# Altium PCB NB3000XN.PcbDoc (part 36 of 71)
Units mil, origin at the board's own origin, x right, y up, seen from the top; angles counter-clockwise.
Board outline 9527.56 x 6929.77 mil, 6 copper layers (Top Layer, GND+SHIELD, MidLayer1, MidLayer2, P2 - 3V3+5V0, Bottom Layer), stack 62.375 mil thick; 832 components, 1027 nets, 4655 pads, 4981 vias.
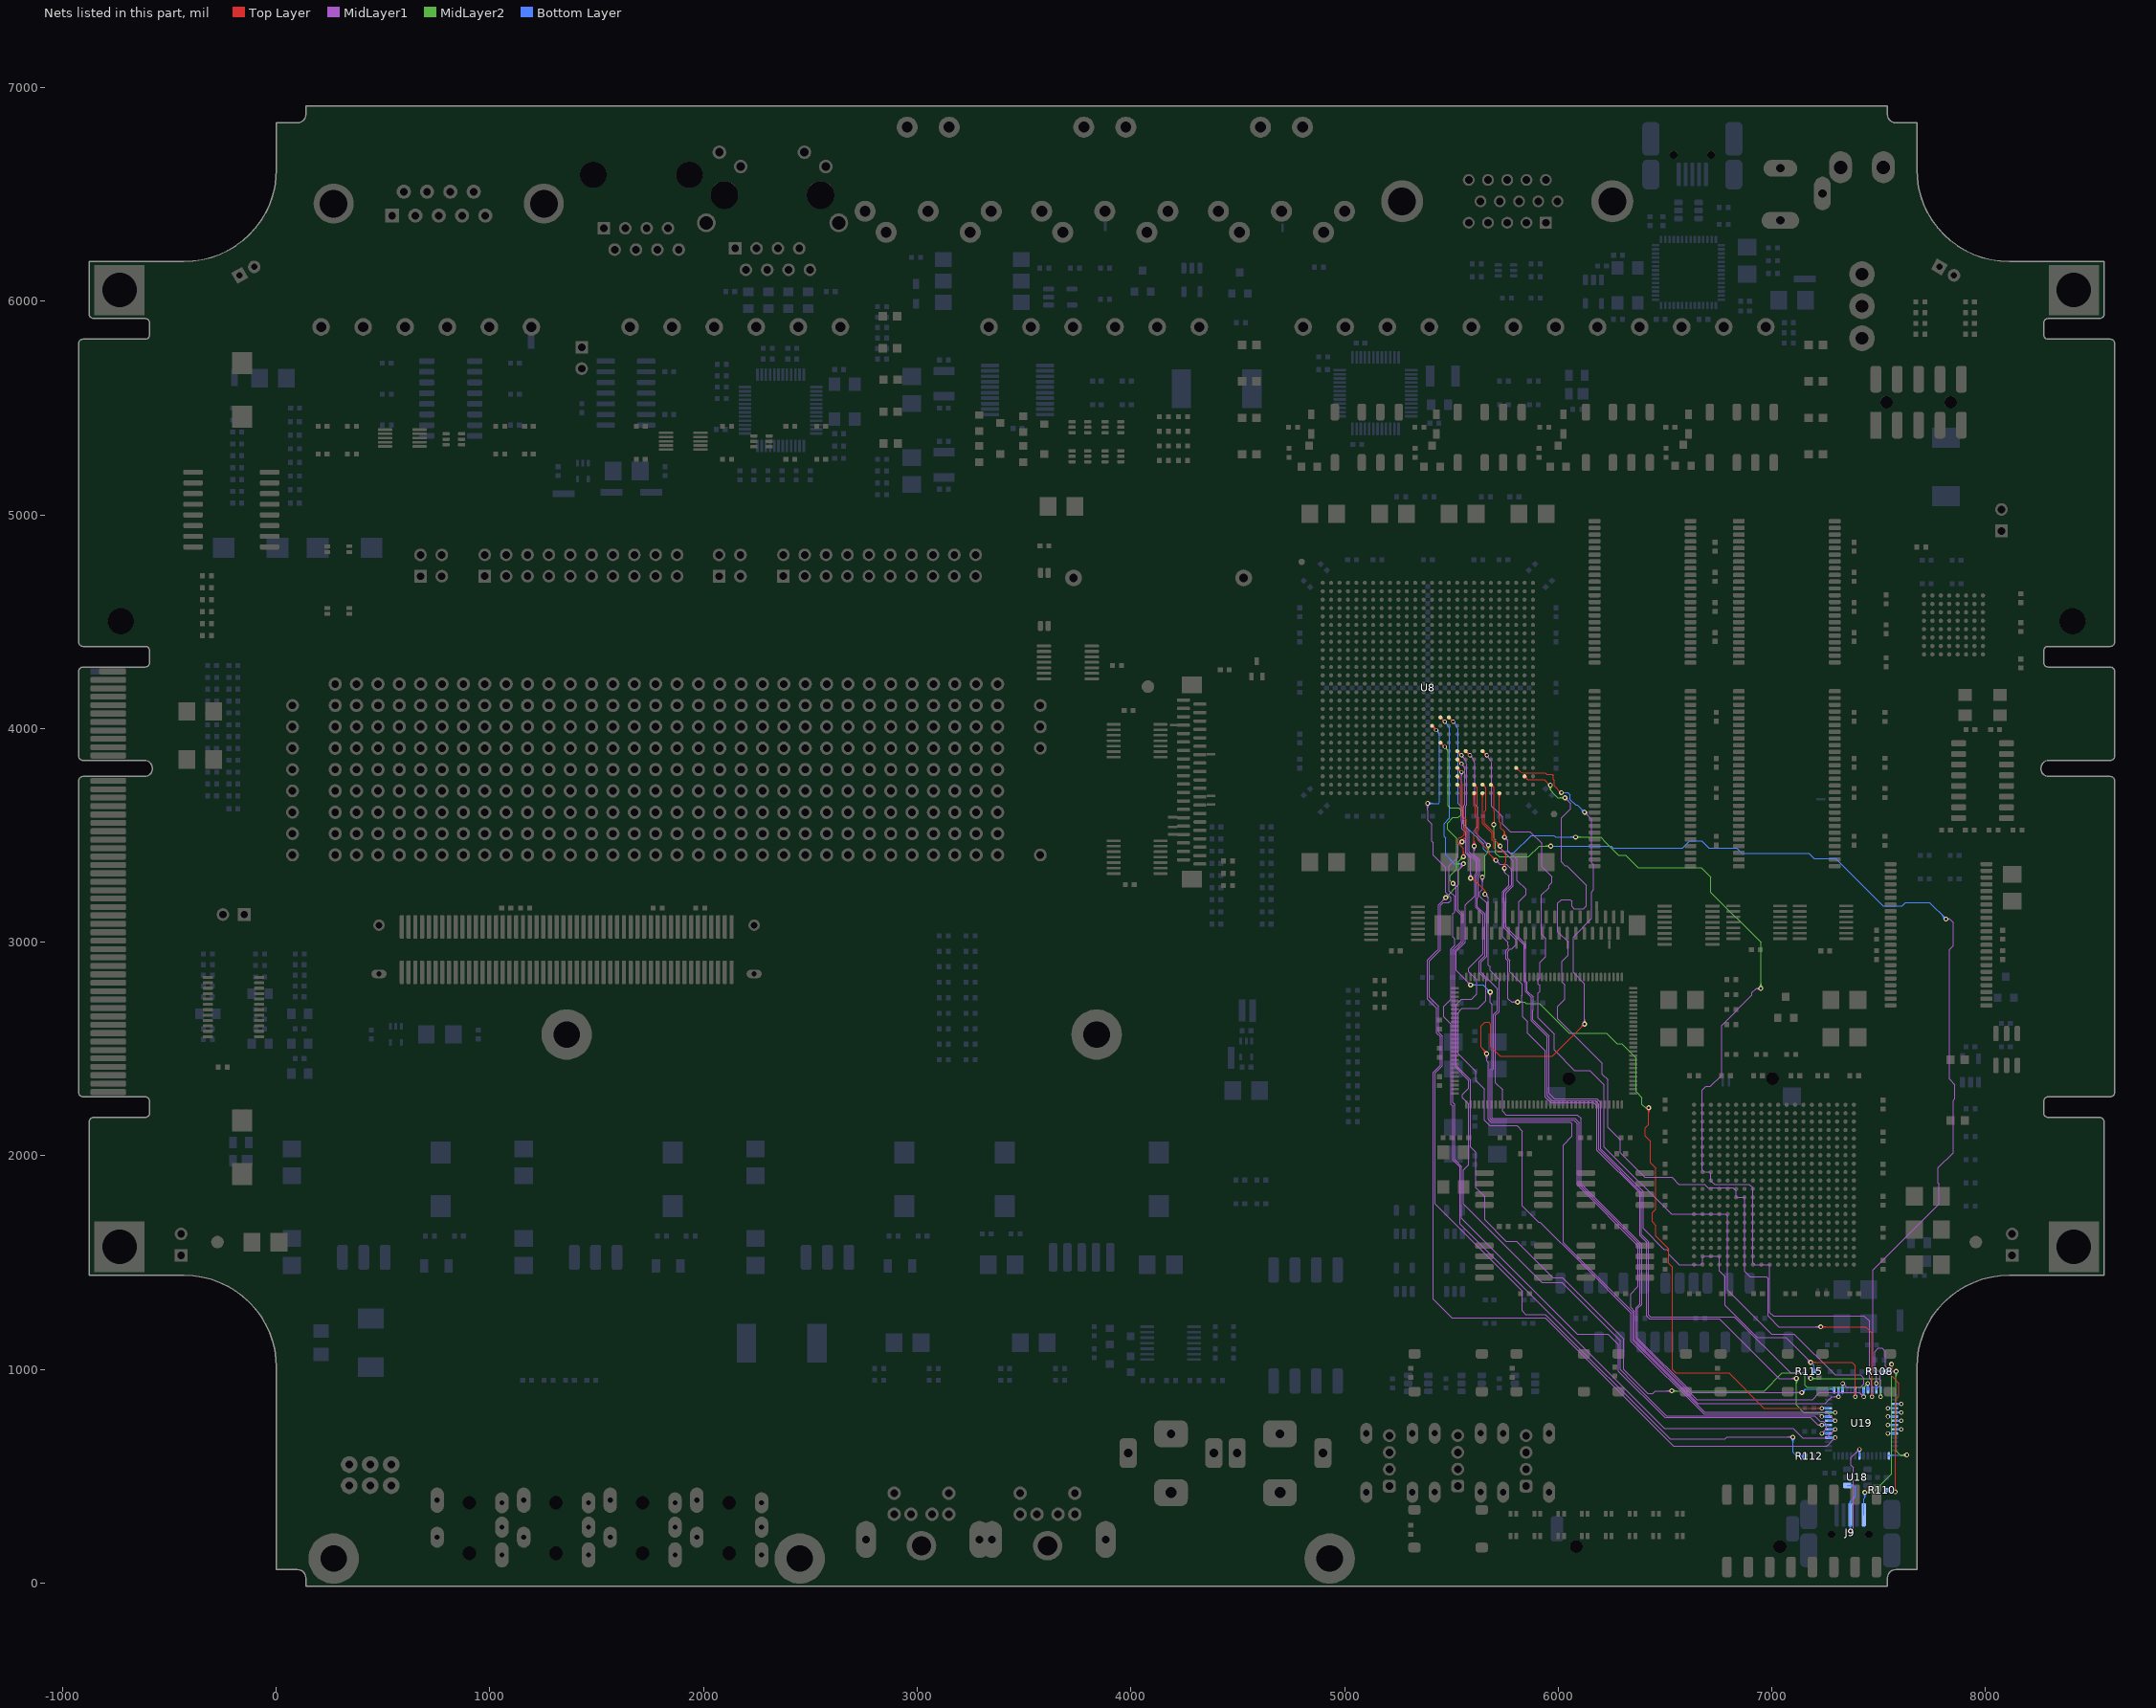
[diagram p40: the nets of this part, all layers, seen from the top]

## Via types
v1: diameter 23, hole 11.81, Top Layer to Bottom Layer, 3672 vias
v2: diameter 26, hole 11.81, Top Layer to Bottom Layer, 461 vias
v3: diameter 19, hole 11.81, Top Layer to Bottom Layer, tented both sides, 396 vias
v4: diameter 23.62, hole 11.81, Top Layer to Bottom Layer, 288 vias
v5: diameter 20, hole 11.81, Top Layer to Bottom Layer, 91 vias
v6: diameter 23, hole 11.81, Top Layer to Bottom Layer, tented both sides, 50 vias
v7: diameter 31, hole 11.81, Top Layer to Bottom Layer, 15 vias
v8: diameter 27.56, hole 11.81, Top Layer to Bottom Layer, tented both sides, 4 vias
v9: diameter 29, hole 11.81, Top Layer to Bottom Layer, 3 vias
v10: diameter 21, hole 11.81, Top Layer to Bottom Layer, 1 vias

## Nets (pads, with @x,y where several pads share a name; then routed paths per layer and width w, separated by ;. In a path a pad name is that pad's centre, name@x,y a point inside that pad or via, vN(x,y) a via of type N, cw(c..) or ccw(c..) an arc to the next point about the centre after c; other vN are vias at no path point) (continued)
DBUSB#.DPLUS: J9.3 U18.1 U19.8 | length 878.2
  MidLayer1 w5: v4(7367.01,242.01) 7381.47,256.47 7381.47,541.46 7370,552.93 7370,586.84 v5(7410.16,627) ; v5@7402.66,627 cw(c7384.55,627) 7397.35,614.2 cw(c7410.16,601.39) v5@7410.16,619.5
  Bottom Layer w5: U18.1@7352.76,457.6 7382.4,457.6 ; v4@7360.42,248.59 ccw(c7344.53,264.49) 7367.01,264.49 ccw(c7389.49,264.49) v4@7373.59,248.59 ; J9.3@7361.82,269.53 cw(c7349.28,257) 7367.01,257 cw(c7384.73,257) J9.3@7372.2,269.53 ; J9.3@7362.04,370.68 ccw(c7351.61,382.01) 7367.01,382.01 ; v4@7365,240 v4(7367.01,242.01) J9.3@7367.01,320 7367.01,382.01 ; U18.1@7367.41,450.47 cw(c7382.4,438.26) 7382.4,457.6 ; U18.1@7367.41,464.72 ccw(c7382.4,476.94) 7382.4,457.6 ; J9.3@7371.98,370.68 cw(c7382.4,382.01) 7367.01,382.01 ; 7367.01,382.01 7389.5,404.5 7389.5,450.5 7382.4,457.6
  Bottom Layer w8: v5@7405.91,622.76 cw(c7395.67,612.51) 7410.16,612.51 cw(c7424.64,612.51) v5@7414.4,622.76 ; U19.8@7410.16,595.67 v5(7410.16,627)
DBUSB#.VBUS: J9.1 R108.2 R110.1 | length 1876.7
  Top Layer w4: v1@7553.51,1018.28 cw(c7537.85,1002.62) 7560,1002.62 ; v1@7556.34,1021.11 cw(c7547.51,1012.28) 7560,1012.28 ; 7560,1001.51 cw(c7583.72,1001.51) v1@7566.95,1018.28 ; 7560,1011.16 cw(c7574.07,1011.16) v1@7564.12,1021.11 ; v1@7560.23,1024.77 7560,1025 7560,970 7595,935 7595,875 7577.85,857.85 v1(7577.85,427.15)
  MidLayer2 w4: v1(7435,425) 7473.48,425 7560.23,511.75 v1(7560.23,1025) ; v1@7438.89,421.11 cw(c7448.28,411.72) 7448.28,425 cw(c7448.28,438.28) v1@7438.89,428.89 ; v1@7441.72,418.28 cw(c7457.94,402.06) 7457.94,425 cw(c7457.94,447.93) v1@7441.72,431.72 ; v1@7553.51,1018.28 cw(c7537.3,1002.06) 7560.23,1002.06 cw(c7583.17,1002.06) v1@7566.95,1018.28 ; v1@7556.34,1021.11 cw(c7546.95,1011.72) 7560.23,1011.72 cw(c7573.51,1011.72) v1@7564.12,1021.11
  Bottom Layer w4: v1@7428.28,418.28 cw(c7412.06,402.06) 7435,402.06 cw(c7457.94,402.06) v1@7441.72,418.28 ; J9.1@7430,320 7430,395 7435,400 v1(7435,425) ; v1@7431.11,421.11 cw(c7421.72,411.72) 7435,411.72 cw(c7448.28,411.72) v1@7438.89,421.11 ; R108.2@7526.18,990 7551.82,990 7560,998.18 7560,1025 v1(7560.23,1025) ; R108.2@7529.94,986.24 cw(c7539.02,977.16) 7539.02,990 cw(c7539.02,1002.84) R108.2@7529.94,993.76 ; R108.2@7532.77,983.41 cw(c7548.68,967.5) 7548.68,990 cw(c7548.68,1012.5) R108.2@7532.77,996.59 ; R110.1@7536.18,435 7555,435 ; R110.1@7543.59,429.35 cw(c7555,420.66) 7555,435 ; R110.1@7543.59,440.65 ccw(c7555,449.34) 7555,435 ; v1@7553.51,1018.28 cw(c7537.85,1002.62) 7560,1002.62 ; v1@7556.34,1021.11 cw(c7547.51,1012.28) 7560,1012.28 ; 7560,1001.51 cw(c7583.72,1001.51) v1@7566.95,1018.28 ; 7560,1011.16 cw(c7574.07,1011.16) v1@7564.12,1021.11 ; v1(7577.85,427.15) 7562.85,427.15 7555,435
DBUSB.D0: U8.AE17 U19.18 | length 5113.6
  Top Layer w4: v1@5550.14,3406.76 ccw(c5533.92,3422.98) 5556.86,3422.98 ccw(c5579.79,3422.98) v1@5563.57,3406.76 ; v1@5552.97,3403.93 ccw(c5543.58,3413.32) 5556.86,3413.32 ccw(c5570.14,3413.32) v1@5560.75,3403.93 ; v1(5556.86,3400.04) 5556.86,3438.04 5531.02,3463.87 5531.02,3482.29 5537.92,3489.19 5545.69,3489.19 5560.81,3504.31 5560.81,3570.31 5551.17,3579.96 5551.17,3621.52 5543.3,3629.39 5543.3,3660 5543.3,3670 5543.3,3717.53 ; 5540.33,3724.71 cw(c5533.15,3717.53) 5543.3,3717.53 ; 5540.33,3724.71 cw(c5533.15,3717.53) 5543.3,3717.53 ; 5540.33,3724.71 ccw(c5527.8,3712.17) 5527.8,3729.9 cw(c5527.8,3712.17) 5540.33,3724.71 ; 5540.33,3724.71 cw(c5552.86,3737.24) 5535.14,3737.24 ccw(c5552.86,3737.24) 5540.33,3724.71
  MidLayer1 w4: v1@5464.02,3208.37 cw(c5441.09,3208.37) 5457.31,3192.16 cw(c5473.52,3175.94) v1@5473.52,3198.87 ; v1@5465.19,3208.37 v1(5473.52,3208.37) 5448.52,3183.37 5440.19,3175.04 5440.19,3044.69 5440.19,3035 5440.19,2967.22 5431.47,2958.5 5431.12,2958.5 5411.5,2938.88 5411.5,2938.53 5389.52,2916.56 5389.52,2734.04 5431.86,2691.71 5431.86,2575.04 5448.52,2558.37 5448.52,2425.04 5415.19,2391.71 5415.19,1329.81 5503.29,1241.71 5940.19,1241.71 6540.19,641.71 7257.6,641.71 v5(7297,681.1) v5@7298.52,681.11 ; v1@5468.02,3208.37 cw(c5454.75,3208.37) 5464.14,3198.99 cw(c5473.52,3189.6) v1@5473.52,3202.87 ; v5@7289,681.1 cw(c7269.69,681.1) 7283.34,667.45 cw(c7297,653.79) v5@7297,673.1
  MidLayer2 w4: v1(5473.52,3208.37) 5535,3269.85 5535,3378.18 v1(5556.86,3400.04) v1@5556.86,3393.37 ; v1@5473.52,3213.87 ccw(c5473.52,3227.15) 5482.91,3217.76 ccw(c5492.3,3208.37) v1@5479.02,3208.37 ; v1@5473.52,3217.87 ccw(c5473.52,3240.81) 5489.74,3224.59 ccw(c5505.96,3208.37) v1@5483.02,3208.37 ; v1@5547.36,3400.04 cw(c5524.42,3400.04) 5540.64,3383.82 cw(c5556.86,3367.61) v1@5556.86,3390.54 ; v1@5551.36,3400.04 cw(c5538.08,3400.04) 5547.47,3390.65 cw(c5556.86,3381.26) v1@5556.86,3394.54
  Bottom Layer w8: U19.18@7265.67,681.1 v5(7297,681.1) ; v5@7292.76,676.86 ccw(c7282.51,666.62) 7282.51,681.1 ccw(c7282.51,695.59) v5@7292.76,685.35
DBUSB.D1: U8.U15 U19.19 | length 5063.4
  Top Layer w4: U8.U15@5449.06,4044.7 cw(c5449.06,4026.6) 5461.86,4039.4 cw(c5474.66,4052.2) U8.U15@5456.56,4052.2 ; U8.U15@5449.06,4044.86 cw(c5449.06,4027.14) 5461.59,4039.67 cw(c5474.12,4052.2) U8.U15@5456.4,4052.2 ; U8.U15@5449.06,4052.2 v3(5468.74,4032.52) ; 5455.94,4045.32 cw(c5443.13,4032.52) 5461.24,4032.52 ccw(c5443.13,4032.52) 5455.94,4045.32 ; 5455.94,4045.32 ccw(c5468.74,4058.13) 5468.74,4040.02 cw(c5468.74,4058.13) 5455.94,4045.32
  MidLayer1 w4: 5535.93,3340.11 ccw(c5508.33,3367.71) v1@5547.36,3367.71 ; 5542.75,3346.94 ccw(c5521.98,3367.71) v1@5551.36,3367.71 ; 5549.58,3353.77 ccw(c5535.64,3367.71) v1@5555.36,3367.71 ; 5552.02,3356.2 cw(c5556.86,3351.37) v1@5556.86,3358.21 ; v1(5556.86,3367.71) 5556.86,3361.04 5531.86,3336.04 5531.86,3152.36 5556.86,3127.36 5556.86,3002.02 5515.19,2960.35 5515.19,2418.69 5581.86,2352.02 5581.86,2317.05 5552.19,2287.38 5552.19,2272.62 5581.86,2242.95 5581.86,1958.37 5556.86,1933.37 5556.86,1775.04 5731.86,1600.04 5923.52,1408.37 6016.82,1408.37 6290.19,1135 6290.19,1000.04 6349.65,940.58 6506.86,783.37 7200,783.37 7225,758.37 7240.19,758.37 7256.86,741.71 7256.86,723.31 v5(7234.34,700.79) ; v5@7234.34,708.79 ccw(c7234.34,728.1) 7247.99,714.44 ccw(c7261.66,700.79) v5@7242.34,700.79
  Bottom Layer w4: v3@5468.09,4025.05 cw(c5466.51,4007.01) 5480.38,4018.65 ; v3@5476.21,4031.87 ccw(c5494.25,4030.29) 5480.38,4018.65 ; v1@5550.14,3360.99 ccw(c5533.92,3344.77) 5533.92,3367.71 ccw(c5533.92,3390.64) v1@5550.14,3374.43 ; v1@5552.97,3363.82 ccw(c5543.58,3354.43) 5543.58,3367.71 ccw(c5543.58,3380.99) v1@5552.97,3371.6 ; v1(5556.86,3367.71) 5514.92,3367.71 5473.19,3409.44 5473.19,3487.36 5465.8,3494.75 5465.8,3555 5492.6,3581.8 5492.6,3660 5492.6,3670 5492.6,3876.1 5492.6,3895.52 5492.6,3969.64 5492.6,3989.14 ccw(c5450.87,3989.14) 5480.38,4018.65
  Bottom Layer w8: v5(7234.34,700.79) U19.19@7265.67,700.79 ; v5@7238.58,696.54 cw(c7248.82,686.3) 7248.82,700.79 cw(c7248.82,715.27) v5@7238.58,705.03
DBUSB.D2: U8.AD17 U19.20 | length 4643.9
  Top Layer w4: v1(5550,3470) 5550,3473.56 5548.52,3475.04 5560.19,3486.71 ; v1@5550,3479.5 ccw(c5550,3486.7) 5555.09,3481.61 ; v1@5554.85,3472.59 cw(c5562.56,3476.71) 5556.38,3482.89 ; v1@5558.38,3474.48 cw(c5567.53,3479.37) 5560.19,3486.71 ; 5540.33,3764.08 cw(c5512.98,3736.73) 5551.66,3736.73 ; 5540.33,3764.08 cw(c5512.98,3736.73) 5551.66,3736.73 ; 5540.33,3764.08 cw(c5552.86,3776.61) 5535.14,3776.61 ccw(c5552.86,3776.61) 5540.33,3764.08 ; 5540.33,3764.08 ccw(c5527.8,3751.55) 5527.8,3769.27 cw(c5527.8,3751.55) 5540.33,3764.08 ; 5551.66,3736.73 5551.66,3670 5551.66,3660 5551.66,3633.34 5559.17,3625.83 5559.17,3620 5559.17,3612.36 5559.17,3583.27 5568.81,3573.63 5568.81,3564 5568.81,3495.33 5560.19,3486.71
  MidLayer1 w4: 5533.74,3460.26 cw(c5545.25,3448.76) v1@5548.8,3464.63 ; 5538.39,3464.91 ccw(c5533.3,3470) v1@5540.5,3470 ; 5538.89,3465.4 cw(c5547.13,3457.16) v1@5549.67,3468.54 ; v1(5550,3470) 5550,3473.56 5548.52,3475.04 5546.74,3473.26 5531.86,3458.37 5531.86,3399.37 5489.86,3357.37 5489.86,3239.67 5515.19,3214.34 5515.19,3141.71 5506.86,3133.37 5506.86,3025.04 5516.19,3015.71 5516.19,2986.19 5498.52,2968.52 5498.52,2733.37 5464.19,2699.04 5464.19,2651.04 5498.52,2616.71 5498.52,2241.71 5506.86,2233.37 5506.86,1980.39 5540.19,1947.06 5540.19,1681.37 6088.19,1133.37 6496.5,725.04 7098.52,725.04 7143.56,680 7256.53,680 v5@7290.19,713.66 ; v5@7289,720.47 cw(c7269.69,720.47) 7283.34,706.82 cw(c7297,693.16) v5@7297,712.47 ; v5@7290.19,713.66 v5(7297,720.47) 7290.19,720.47 v5@7290.19,713.66
  Bottom Layer w8: U19.20@7265.67,720.47 v5(7297,720.47) ; v5@7292.76,716.23 ccw(c7282.51,705.99) 7282.51,720.47 ccw(c7282.51,734.96) v5@7292.76,724.72
DBUSB.D3: U8.Y15 U19.21 | length 4912.9
  Top Layer w4: U8.Y15@5449.06,3926.59 cw(c5449.06,3908.49) 5461.86,3921.29 cw(c5474.66,3934.09) U8.Y15@5456.56,3934.09 ; U8.Y15@5449.06,3926.75 cw(c5449.06,3909.03) 5461.59,3921.56 cw(c5474.12,3934.09) U8.Y15@5456.4,3934.09 ; U8.Y15@5449.06,3934.09 v3(5468.74,3914.41) ; 5455.94,3927.21 cw(c5443.13,3914.41) 5461.24,3914.41 ccw(c5443.13,3914.41) 5455.94,3927.21 ; 5455.94,3927.21 ccw(c5468.74,3940.02) 5468.74,3921.91 cw(c5468.74,3940.02) 5455.94,3927.21
  MidLayer1 w4: 5506.7,2919.53 5506.7,2963.17 5548.52,3005 5548.52,3124.37 5523.52,3149.37 5523.52,3259.04 ; 5506.86,2919.53 5506.86,2250.04 5515.19,2241.71 5515.19,1983.37 5548.52,1950.04 5548.52,1708.37 6090.19,1166.71 6231.86,1166.71 6281.86,1116.71 6281.86,991.71 6498.52,775.04 7179.96,775.04 7214.84,740.16 ; v1(5507.52,3275.04) 5523.52,3259.04 ; v1@5507.58,3269.54 cw(c5507.7,3256.69) 5516.79,3265.78 cw(c5525.87,3274.86) v1@5513.02,3274.99 ; v1@5507.62,3265.54 cw(c5507.83,3243.35) 5523.52,3259.04 ; v1@5517.02,3274.95 ccw(c5539.22,3274.74) 5523.52,3259.04 ; 7215,740 7214.84,740.16 ; v5@7228.68,734.5 ccw(c7215.03,720.85) 7215.03,740.16 ccw(c7215.02,759.47) v5@7228.68,745.81 ; v5(7234.34,740.16) 7214.84,740.16
  MidLayer2 w4: v3@5468.09,3906.94 cw(c5466.51,3888.9) 5480.38,3900.54 cw(c5494.25,3912.18) v3@5476.21,3913.76 ; 5480.13,3900.83 cw(c5470.2,3890.9) 5484.25,3890.9 ; 5484.25,3680.84 5484.25,3739.1 ; 5484.25,3876.97 5484.25,3890.9 ; v1(5507.52,3275.04) 5493.52,3289.04 5493.52,3311.71 5524.02,3342.21 5524.02,3486.17 5481.86,3528.33 5481.86,3558.37 5506.86,3583.37 5532.86,3583.37 5544.52,3595.04 5544.52,3617.04 5533.56,3628 5493.29,3628 5484.25,3637.04 5484.25,3660 5484.25,3670 5484.25,3739.1 ; 5484.25,3739.1 5484.25,3797.36 5484.25,3890.9
  Bottom Layer w8: v5(7234.34,740.16) U19.21@7265.67,740.16 ; v5@7238.58,735.91 cw(c7248.82,725.67) 7248.82,740.16 cw(c7248.82,754.64) v5@7238.58,744.4
DBUSB.D4: U8.AC24 U19.22 | length 5835.8
  Top Layer w4: 5645.2,2503.36 cw(c5619.88,2478.04) v1@5655.69,2478.04 ; 5652.03,2496.54 cw(c5633.53,2478.04) v1@5659.69,2478.04 ; 5658.08,2490.49 ccw(c5665.19,2497.6) v1@5665.19,2487.54 ; 5658.86,2489.71 cw(c5647.19,2478.04) v1@5663.69,2478.04 ; v1(5665.19,2478.04) 5665.19,2483.37 5640.19,2508.37 5640.19,2608.37 5656.86,2625.04 5675,2625.04 5685,2615.04 5685,2510 5728.29,2466.71 5973.52,2466.71 v1(6123.52,2616.71) ; 5971.94,3784.71 5976.5,3780.15 ; v1(6015.19,3700.04) 6012.14,3700.04 5981.19,3731 5981.19,3756.43 5976.5,3761.12 5976.5,3780.15 ; v1@6114.02,2616.71 cw(c6091.09,2616.71) 6107.31,2600.49 cw(c6123.52,2584.27) v1@6123.52,2607.21 ; v1@6118.02,2616.71 cw(c6104.75,2616.71) 6114.14,2607.32 cw(c6123.52,2597.93) v1@6123.52,2611.21 ; 5815.92,3803.45 ccw(c5803.39,3790.92) 5803.39,3808.64 cw(c5803.39,3790.92) 5815.92,3803.45 ; 5815.92,3803.45 cw(c5828.45,3815.98) 5810.73,3815.98 ccw(c5828.45,3815.98) 5815.92,3803.45 ; 5843.27,3792.12 cw(c5843.27,3830.8) 5815.92,3803.45 ccw(c5843.27,3830.8) 5843.27,3792.12 ; 5843.27,3792.12 5910,3792.12 5920,3792.12 5939.38,3792.12 5946.29,3785.21 5971.44,3785.21 5976.5,3780.15
  MidLayer1 w4: v1@5658.47,2471.32 cw(c5642.26,2455.11) 5665.19,2455.11 cw(c5688.13,2455.11) v1@5671.91,2471.32 ; v1@5661.3,2474.15 cw(c5651.91,2464.76) 5665.19,2464.76 cw(c5678.47,2464.76) v1@5669.08,2474.15 ; v1(5665.19,2478.04) 5665.19,2444.69 5673.52,2436.35 5673.52,2172.06 5687.21,2158.37 6056.86,2158.37 6065.19,2150.04 6065.19,2092.71 6023.52,2051.04 6023.52,1593.02 6348.52,1268.02 6348.52,1136.35 6684.84,800.04 7256.8,800.04 v5(7297,759.84) 7298.52,759.84 v5@7298.52,766.71 ; v1@6116.81,2623.43 ccw(c6100.59,2639.64) 6123.52,2639.64 ccw(c6146.46,2639.64) v1@6130.24,2623.43 ; v1@6119.64,2620.6 ccw(c6110.25,2629.99) 6123.52,2629.99 ccw(c6136.8,2629.99) v1@6127.41,2620.6 ; v1(6123.52,2616.71) 6123.52,2805.71 6070.86,2858.37 6070.86,3025.04 6156.86,3111.04 6156.86,3210 6156.86,3235.69 6166.19,3245.02 6166.19,3250.04 6166.19,3275 6166.19,3362.12 6156.86,3371.45 6156.86,3575.04 v1(6123.52,3608.37) ; v1@6123.52,3598.87 cw(c6123.52,3575.94) 6139.74,3592.16 cw(c6155.96,3608.37) v1@6133.02,3608.37 ; v1@6123.52,3602.87 cw(c6123.52,3589.6) 6132.91,3598.99 cw(c6142.3,3608.37) v1@6129.02,3608.37 ; v5@7289,759.84 ccw(c7269.69,759.84) 7283.34,773.5 ccw(c7297,787.16) v5@7297,767.84
  Bottom Layer w4: v1(6015.19,3700.04) 6045.18,3700.03 6056.86,3688.37 6056.86,3666.71 6081.86,3641.71 6090.19,3641.71 v1(6123.52,3608.37) ; v1@6114.02,3608.37 ccw(c6091.09,3608.37) 6107.31,3624.59 ccw(c6123.52,3640.81) v1@6123.52,3617.87 ; v1@6118.02,3608.37 ccw(c6104.75,3608.37) 6114.13,3617.76 ccw(c6123.52,3627.15) v1@6123.52,3613.87
  Bottom Layer w8: U19.22@7265.67,759.84 v5(7297,759.84) ; v5@7292.76,755.6 ccw(c7282.51,745.36) 7282.51,759.84 ccw(c7282.51,774.33) v5@7292.76,764.09
DBUSB.D5: U8.AF19 U19.23 | length 4406.9
  Top Layer w4: v1@5600.14,3456.76 ccw(c5583.92,3472.98) 5606.86,3472.98 ccw(c5629.79,3472.98) v1@5613.57,3456.76 ; U8.AF19@5601.23,3692.57 cw(c5588.43,3679.77) 5606.54,3679.77 cw(c5624.64,3679.77) U8.AF19@5611.84,3692.57 ; U8.AF19@5601.34,3692.68 cw(c5588.81,3680.15) 5606.54,3680.15 cw(c5624.26,3680.15) U8.AF19@5611.73,3692.68 ; v1@5602.97,3453.93 ccw(c5593.58,3463.32) 5606.86,3463.32 ccw(c5620.14,3463.32) v1@5610.75,3453.93 ; U8.AF19@5606.54,3697.87 5606.54,3670 5606.54,3660 5606.54,3637.11 5611.69,3631.96 5611.69,3586.87 5620,3578.56 5620,3534.23 5606.86,3521.09 v1(5606.86,3450.04)
  MidLayer1 w4: v1@5600.14,3443.32 cw(c5583.92,3427.11) 5606.86,3427.11 cw(c5629.79,3427.11) v1@5613.57,3443.32 ; v1@5602.97,3446.15 cw(c5593.58,3436.76) 5606.86,3436.76 cw(c5620.14,3436.76) v1@5610.75,3446.15 ; v1(5606.86,3450.04) 5606.86,3410.32 5632.19,3384.98 5632.19,3316.94 5625.19,3309.94 5625.19,3211.04 5622.52,3208.37 5622.52,3166.04 5657.19,3131.37 5657.19,2937.69 5630,2910.5 5630,2857.25 5660.86,2826.39 5660.86,2725.86 5625,2690 5550,2690 5531.19,2671.19 5531.19,2478 5615.19,2394 5615.19,2352.63 5655.41,2312.41 5655.41,2166.3 5680,2141.71 5806.86,2141.71 5832.5,2116.06 5832.5,1766.06 5908.52,1690.04 5915.19,1690.04 6113.52,1491.71 6340.52,1264.71 6340.52,1133.04 6681.86,791.71 7200,791.71 7222.16,791.71 v5(7234.34,779.53) 7231.86,779.52 v5@7231.86,779.71
  Bottom Layer w8: v5(7234.34,779.53) U19.23@7265.67,779.53 ; v5@7238.58,775.28 cw(c7248.82,765.04) 7248.82,779.53 cw(c7248.82,794.01) v5@7238.58,783.77
DBUSB.D6: U8.AE19 U19.24 | length 4633.8
  Top Layer w4: U8.AE19@5606.54,3729.9 cw(c5606.54,3712.17) 5619.07,3724.71 ; U8.AE19@5613.88,3737.24 ccw(c5631.6,3737.24) 5619.07,3724.71 ; v1@5698.56,3383.58 ccw(c5675.63,3383.58) 5691.85,3399.8 ccw(c5708.06,3416.02) v1@5708.06,3393.08 ; v1@5702.56,3383.58 ccw(c5689.29,3383.58) 5698.67,3392.97 ccw(c5708.06,3402.36) v1@5708.06,3389.08 ; v1@5706.86,3384.79 5677.36,3414.28 5677.36,3424.2 5623.52,3478.04 5623.52,3525 5628,3529.48 5628,3581.88 5622.04,3587.84 5622.04,3660 5622.04,3670 5622.04,3717.53 ccw(c5611.89,3717.53) 5619.07,3724.71
  MidLayer1 w4: v1@5706.86,3382.37 v1(5708.06,3383.58) 5727.6,3364.04 5757.52,3364.04 5781.86,3339.71 5781.86,3268.04 5747.86,3234.04 5747.86,3067.33 5803.48,3011.71 5803.48,2988.29 5782.73,2967.54 5774.61,2967.54 5764.36,2957.29 5764.36,2924.11 5773.19,2915.28 5773.19,2860.5 5827,2806.69 ; v1@5708.06,3374.08 cw(c5708.06,3351.15) 5724.28,3367.36 cw(c5740.5,3383.58) v1@5717.56,3383.58 ; v1@5708.06,3378.08 cw(c5708.06,3364.8) 5717.45,3374.19 cw(c5726.84,3383.58) v1@5713.56,3383.58 ; 5787.06,2846.63 5831.36,2802.32 5831.36,2752.26 5829.19,2750.09 5829.19,2724.31 5833.69,2719.81 5833.69,2650.21 ; v1@7108.47,951.66 ccw(c7092.26,935.44) 7092.26,958.37 ccw(c7092.26,981.31) v1@7108.47,965.09 ; v1@7111.3,954.49 ccw(c7101.91,945.1) 7101.91,958.37 ccw(c7101.91,971.65) v1@7111.3,962.26 ; v1(7115.19,958.37) 7065,958.37 7048.52,958.37 7034.84,958.37 6755.21,1238 6702,1238 6428.31,1238 6414.81,1251.5 6414.81,1595.07 6382.19,1627.69 6382.19,1826.1 6181.86,2026.43 6181.86,2233.37 6165.19,2250.04 5965.19,2250.04 5940.19,2275.04 5940.19,2491.71 5856.86,2575.04 5856.86,2627.04 ; 5833.69,2650.21 5856.86,2627.04 ; 5833.69,2650.21 5856.86,2627.04
  MidLayer2 w4: v1@7108.47,951.66 cw(c7092.26,935.44) 7115.19,935.44 cw(c7138.13,935.44) v1@7121.91,951.66 ; v1@7111.3,954.49 cw(c7101.91,945.1) 7115.19,945.1 cw(c7128.47,945.1) v1@7119.08,954.49 ; v1(7115.19,958.37) 7115.19,833.37 7149.35,799.21 v5(7297,799.21) ; v5@7291.34,793.56 ccw(c7277.68,779.89) 7277.68,799.21 ccw(c7277.69,818.52) v5@7291.34,804.87
  Bottom Layer w8: U19.24@7282.51,799.21 cw(c7282.51,784.73) 7292.76,794.97 ccw(c7282.51,784.73) U19.24@7282.51,799.21 ; U19.24@7282.51,799.21 ccw(c7282.51,813.7) 7292.76,803.46 cw(c7282.51,813.7) U19.24@7282.51,799.21 ; U19.24@7265.67,799.21 v5(7297,799.21) U19.24@7265.67,799.21
DBUSB.D7: U8.AF20 U19.25 | length 4530.8
  Top Layer w4: U8.AF20@5640.6,3692.57 cw(c5627.8,3679.77) 5645.91,3679.77 cw(c5664.01,3679.77) U8.AF20@5651.21,3692.57 ; U8.AF20@5645.91,3697.87 5645.91,3670 5645.91,3660 5645.91,3555.41 5690.86,3510.46 5690.86,3478.33 5699.19,3470 5699.19,3441.71 5715.86,3425.04 5740.19,3425.04 5756.86,3408.37 5756.86,3375 5748.52,3366.67 ; v1@5742.44,3353.67 ccw(c5731.6,3366.67) 5748.52,3366.67 ; v1@5745,3350.6 ccw(c5738.73,3358.12) 5748.52,3358.12 ccw(c5758.32,3358.12) v1@5752.05,3350.6 ; v1(5748.52,3346.37) 5748.52,3366.67 ; v1@5754.61,3353.67 cw(c5765.44,3366.67) 5748.52,3366.67 ; v1@6416.81,2218.32 cw(c6400.59,2202.11) 6423.52,2202.11 cw(c6446.46,2202.11) v1@6430.24,2218.32 ; v1@6419.64,2221.15 cw(c6410.25,2211.76) 6423.52,2211.76 cw(c6436.8,2211.76) v1@6427.41,2221.15 ; v1(6423.52,2225.04) 6423.52,2146.67 6406.86,2130 6406.86,2093.33 6431.86,2068.33 6431.86,1966.71 6456.86,1941.71 6456.86,1750.04 6440.19,1733.37 6440.19,1691.71 6456.86,1675.04 6456.86,1625.04 6518.19,1563.71 6518.19,1496.81 6535,1480 6535,1000 6551.63,983.37 6798.52,983.37 6956.86,825.04 6963,818.9 v5(7234.34,818.9) ; v5@7228.68,813.24 ccw(c7215.02,799.58) 7215.02,818.9 ccw(c7215.02,838.21) v5@7228.68,824.55 ; 5645.91,3680.15 cw(c5663.63,3680.15) 5651.1,3692.68 ccw(c5663.63,3680.15) 5645.91,3680.15 ; 5645.91,3680.15 ccw(c5628.18,3680.15) 5640.71,3692.68 cw(c5628.18,3680.15) 5645.91,3680.15
  MidLayer1 w4: v1@5742.93,3338.69 cw(c5734.94,3327.71) 5748.52,3327.71 ; v1(5748.52,3346.37) 5748.52,3327.71 ; v1@5754.12,3338.69 ccw(c5762.11,3327.71) 5748.52,3327.71 ; v1@5803.28,2713.28 ccw(c5787.06,2697.06) 5787.06,2720 ccw(c5787.06,2742.93) v1@5803.28,2726.72 ; v1@5806.11,2716.11 ccw(c5796.72,2706.72) 5796.72,2720 ccw(c5796.72,2733.28) v1@5806.11,2723.89 ; v1(5810,2720) 5781.55,2720 5765,2736.55 5765,2912.15 5756.36,2920.8 5756.36,2960.6 5768,2972.25 5768,2983.79 5765,2986.79 5765,3000 5739.86,3025.14 5739.86,3237.35 5768.19,3265.69 5768.19,3308.04 5748.52,3327.71
  MidLayer2 w4: v1(5810,2720) 5843.77,2720 5850,2713.77 5913.54,2713.77 6052.31,2575 6225.04,2575 6275,2525.04 6298.52,2525.04 6365.19,2458.37 6365.19,2300.04 6392.86,2272.37 6392.86,2241.71 6409.52,2225.04 v1(6423.52,2225.04) ; v1@5813.89,2716.11 cw(c5823.28,2706.72) 5823.28,2720 cw(c5823.28,2733.28) v1@5813.89,2723.89 ; v1@5816.72,2713.28 cw(c5832.93,2697.06) 5832.93,2720 cw(c5832.93,2742.93) v1@5816.72,2726.72
  Bottom Layer w8: v5(7234.34,818.9) U19.25@7265.67,818.9 ; v5@7238.58,814.66 cw(c7248.82,804.41) 7248.82,818.9 cw(c7248.82,833.38) v5@7238.58,823.14
DBUSB.D8: U19.45 | length 54.1
  Bottom Layer w8: U19.45@7574.33,838.58 v5(7605.66,838.58) ; v5@7601.42,834.34 ccw(c7591.18,824.1) 7591.18,838.58 ccw(c7591.18,853.07) v5@7601.42,842.83
DBUSB.D9: U19.46 | length 54.1
  Bottom Layer w8: v5(7543,818.9) U19.46@7574.33,818.9 ; v5@7547.24,814.65 cw(c7557.48,804.41) 7557.48,818.9 cw(c7557.49,833.38) v5@7547.24,823.14
DBUSB.D10: U19.47 | length 54.1
  Bottom Layer w8: U19.47@7574.33,799.21 v5(7605.66,799.21) ; v5@7601.42,794.97 ccw(c7591.18,784.73) 7591.18,799.21 ccw(c7591.18,813.7) v5@7601.42,803.46
DBUSB.D11: U19.48 | length 54.1
  Bottom Layer w8: v5(7543,779.53) U19.48@7574.33,779.53 ; v5@7547.24,775.28 cw(c7557.48,765.04) 7557.48,779.53 cw(c7557.49,794.01) v5@7547.24,783.77
DBUSB.D12: U19.49 | length 54.1
  Bottom Layer w8: U19.49@7574.33,759.84 v5(7605.66,759.84) ; v5@7601.42,755.6 ccw(c7591.18,745.36) 7591.18,759.84 ccw(c7591.18,774.33) v5@7601.42,764.09
DBUSB.D13: U19.50 | length 54.1
  Bottom Layer w8: v5(7543,740.16) U19.50@7574.33,740.16 ; v5@7547.24,735.91 cw(c7557.48,725.67) 7557.48,740.16 cw(c7557.49,754.64) v5@7547.24,744.4
DBUSB.D14: U19.51 | length 54.1
  Bottom Layer w8: U19.51@7574.33,720.47 v5(7605.66,720.47) ; v5@7601.42,716.23 ccw(c7591.18,705.99) 7591.18,720.47 ccw(c7591.18,734.96) v5@7601.42,724.72
DBUSB.D15: U19.52 | length 54.1
  Bottom Layer w8: v5(7543,700.79) U19.52@7574.33,700.79 ; v5@7547.24,696.54 cw(c7557.48,686.3) 7557.48,700.79 cw(c7557.49,715.27) v5@7547.24,705.03
DBUSB.FIFOADR0: U8.AA17 U19.37 | length 5078.7
  Top Layer w4: U8.AA17@5527.8,3887.22 cw(c5527.8,3869.12) 5540.6,3881.92 cw(c5553.4,3894.72) U8.AA17@5535.3,3894.72 ; U8.AA17@5527.8,3887.38 cw(c5527.8,3869.66) 5540.33,3882.19 cw(c5552.86,3894.72) U8.AA17@5535.14,3894.72 ; U8.AA17@5527.8,3894.72 v3(5547.48,3875.04) ; 5534.68,3887.84 cw(c5521.87,3875.04) 5539.98,3875.04 ccw(c5521.87,3875.04) 5534.68,3887.84 ; 5534.68,3887.84 ccw(c5547.48,3900.65) 5547.48,3882.54 cw(c5547.48,3900.65) 5534.68,3887.84
  MidLayer1 w4: v3@5546.83,3867.57 cw(c5545.25,3849.53) 5559.12,3861.17 ; v3@5554.95,3874.39 ccw(c5572.99,3872.81) 5559.12,3861.17 ; 5571.34,3798.23 5571.34,3812.16 ; 6340,966.71 6418.21,888.5 6443.91,888.5 6455.45,900.04 v1(6531.86,900.04) ; 6340.19,966.71 6306.86,1000.04 6306.86,1143.14 6020,1430 5975,1430 5804.96,1600.04 5756.86,1600.04 5656.86,1700.04 5656.86,1808.37 5615.19,1850.04 5615.19,2016.71 5590.19,2041.71 5590.19,2355 5523.19,2422 5523.19,2708.04 5548.52,2733.37 5593.52,2733.37 5618.52,2758.37 5618.52,2825.04 5581.86,2861.71 5581.86,2878.37 5648.48,2945 5648.48,3128.77 5614.52,3162.73 5614.52,3211.69 5617.19,3214.35 5617.19,3313.25 5624.19,3320.25 5624.19,3381.67 5583.69,3422.17 5583.69,3521.31 5567.19,3537.81 5567.19,3638.31 5571.34,3642.47 5571.34,3660 5571.34,3670 5571.34,3718.62 5571.34,3738.04 5571.34,3812.16 ; v1@6525.14,893.32 ccw(c6508.92,877.11) 6508.92,900.04 ccw(c6508.92,922.98) v1@6525.14,906.76 ; v1@6527.97,896.15 ccw(c6518.58,886.76) 6518.58,900.04 ccw(c6518.58,913.32) v1@6527.97,903.93 ; 5559.12,3861.17 cw(c5529.61,3831.66) 5571.34,3831.66 5571.34,3812.16
  MidLayer2 w4: v1(6531.86,900.04) 6965.19,900.04 7048.52,983.37 7141.63,983.37 7155,970 7155,925 7163.29,916.71 7431.86,916.71 7448.52,933.37 7448.52,935.65 v5(7449.53,935.66) ; v1@6535.75,896.15 cw(c6545.14,886.76) 6545.14,900.04 cw(c6545.14,913.32) v1@6535.75,903.93 ; v1@6538.57,893.32 cw(c6554.79,877.11) 6554.79,900.04 cw(c6554.79,922.98) v1@6538.57,906.76 ; 7434.96,919.81 ccw(c7419.12,935.66) v5@7441.53,935.66 ; 7438.06,922.91 cw(c7449.53,911.45) v5@7449.53,927.66 ; 7441.79,926.64 ccw(c7432.77,935.66) v5@7445.53,935.66
  Bottom Layer w8: v5@7445.28,931.42 cw(c7435.04,921.18) 7449.53,921.18 cw(c7464.01,921.18) v5@7453.77,931.42 ; U19.37@7449.53,904.33 v5(7449.53,935.66)
DBUSB.FIFOADR1: U8.AD25 U19.38 | length 4934.4
  Top Layer w4: 5925.54,3761.11 5924.74,3761.11 ; v1(5963.69,3735.37) 5959.88,3735.37 5934.15,3761.11 5924.74,3761.11 ; v1(7228.52,1200.04) 7439.96,1200.04 7469.21,1170.79 v5(7469.21,873) 7469.21,875.04 v5@7473.52,875.04 ; v1@7232.41,1196.15 cw(c7241.8,1186.76) 7241.8,1200.04 cw(c7241.8,1213.32) v1@7232.41,1203.93 ; v1@7235.24,1193.32 cw(c7251.46,1177.11) 7251.46,1200.04 cw(c7251.46,1222.98) v1@7235.24,1206.76 ; v5@7463.56,878.66 ccw(c7449.9,892.31) 7469.21,892.31 ccw(c7488.53,892.31) v5@7474.87,878.66 ; 5855.29,3764.08 ccw(c5862.47,3771.26) 5862.47,3761.11 ; 5855.29,3764.08 ccw(c5862.47,3771.26) 5862.47,3761.11 ; 5855.29,3764.08 cw(c5867.83,3776.61) 5850.1,3776.61 ccw(c5867.83,3776.61) 5855.29,3764.08 ; 5855.29,3764.08 ccw(c5842.76,3751.55) 5842.76,3769.27 cw(c5842.76,3751.55) 5855.29,3764.08 ; 5862.47,3761.11 5910,3761.11 5920,3761.11 5924.74,3761.11
  MidLayer1 w4: v1@6031.86,3666.54 cw(c6031.86,3643.61) 6048.07,3659.82 cw(c6064.29,3676.04) v1@6041.36,3676.04 ; v1@6031.86,3670.54 cw(c6031.86,3657.26) 6041.25,3666.65 cw(c6050.64,3676.04) v1@6037.36,3676.04 ; v1(6031.86,3676.04) 6057.86,3650.04 6057.86,3625.04 6015.19,3582.37 6015.19,3375.04 6031.86,3358.37 6040.19,3358.37 6131.86,3266.71 6131.86,3171.04 6117.92,3157.1 6074.79,3157.1 6065.19,3166.71 6065.19,3191.71 6056.86,3200.04 6015.19,3200.04 5998.52,3183.37 5998.52,3050.04 6045.81,3002.75 6045.81,2939 6017.19,2910.37 6017.19,2814.71 6031.86,2800.04 6031.86,2733.37 5998.52,2700.04 5998.52,2641.71 6206.86,2433.37 6206.86,2382.04 6231.86,2357.04 6231.86,2133.37 6290.19,2075.04 6290.19,2014.37 6404.52,1900.04 6531.86,1900.04 6565.19,1866.71 6684.86,1866.71 6701.52,1850.04 6818.19,1850.04 6833.19,1835.04 6833.19,1808.37 6835.52,1806.04 6870.19,1806.04 6872.19,1804.04 6872.19,1458.37 6897.19,1433.37 6973.82,1433.37 6982.19,1425 6982.19,1250.37 7032.52,1200.04 v1(7228.52,1200.04) ; v1@7221.81,1193.32 ccw(c7205.59,1177.11) 7205.59,1200.04 ccw(c7205.59,1222.98) v1@7221.81,1206.76 ; v1@7224.64,1196.15 ccw(c7215.25,1186.76) 7215.25,1200.04 ccw(c7215.25,1213.32) v1@7224.64,1203.93
  MidLayer2 w4: v1@5956.97,3728.66 cw(c5940.75,3712.44) 5963.69,3712.44 cw(c5986.62,3712.44) v1@5970.41,3728.66 ; v1@5959.8,3731.49 cw(c5950.41,3722.1) 5963.69,3722.1 cw(c5976.97,3722.1) v1@5967.58,3731.49 ; v1(5963.69,3735.37) 5963.69,3710.88 5982.07,3692.5 ; 5971.52,3703.04 5998.52,3676.04 v1(6031.86,3676.04) ; v1@6025.14,3669.32 ccw(c6008.92,3653.11) 6008.92,3676.04 ccw(c6008.92,3698.98) v1@6025.14,3682.76 ; v1@6027.97,3672.15 ccw(c6018.58,3662.76) 6018.58,3676.04 ccw(c6018.58,3689.32) v1@6027.97,3679.93
  Bottom Layer w8: v5@7464.97,877.24 ccw(c7454.73,887.49) 7469.21,887.49 ccw(c7483.7,887.48) v5@7473.46,877.24 ; v5(7469.21,873) U19.38@7469.21,904.33
DBUSB.FIFOADR2: U8.AA18 U19.36 | length 5006.5
  Top Layer w4: U8.AA18@5567.17,3887.22 cw(c5567.17,3869.12) 5579.97,3881.92 cw(c5592.77,3894.72) U8.AA18@5574.67,3894.72 ; U8.AA18@5567.17,3887.38 cw(c5567.17,3869.66) 5579.7,3882.19 cw(c5592.23,3894.72) U8.AA18@5574.51,3894.72 ; U8.AA18@5567.17,3894.72 v3(5586.85,3875.04) ; 5574.05,3887.84 cw(c5561.24,3875.04) 5579.35,3875.04 ccw(c5561.24,3875.04) 5574.05,3887.84 ; 5574.05,3887.84 ccw(c5586.85,3900.65) 5586.85,3882.54 cw(c5586.85,3900.65) 5574.05,3887.84
  MidLayer1 w4: v3@5586.2,3867.57 cw(c5584.62,3849.53) 5598.49,3861.17 ; v3@5594.32,3874.39 ccw(c5612.36,3872.81) 5598.49,3861.17 ; 5610.71,3798.23 5610.71,3812.16 ; v1@5638.28,3298.28 cw(c5622.06,3282.06) 5645,3282.06 cw(c5667.93,3282.06) v1@5651.72,3298.28 ; 5640.19,3242.71 5633.19,3235.71 ; v1@5641.11,3301.11 cw(c5631.72,3291.72) 5645,3291.72 cw(c5658.28,3291.72) v1@5648.89,3301.11 ; v1(5645,3305) 5645,3247.52 5633.19,3235.71 ; 5655.03,3471.2 ccw(c5673.52,3489.7) v1@5673.52,3463.54 ; 5658.25,3467.98 cw(c5644.31,3454.04) v1@5664.02,3454.04 ; 5661.86,3464.37 ccw(c5673.52,3476.04) v1@5673.52,3459.54 ; v1(5673.52,3454.04) 5672.19,3454.04 5615.19,3511.04 5615.19,3533.37 5624.52,3542.71 5624.52,3631.79 5610.71,3645.6 5610.71,3660 5610.71,3670 5610.71,3718.62 5610.71,3738.04 5610.71,3812.16 ; v5@7421.84,873 ccw(c7402.52,873) 7416.18,886.66 ccw(c7429.84,900.31) v5@7429.84,881 ; v5@7429.84,875.04 v5(7429.84,873) 7411.14,891.71 7223.52,891.71 7190.19,858.37 6649.13,858.37 6364.52,1142.98 6364.52,1289.52 6382.81,1307.81 6382.81,1581.81 6098.52,1866.1 6098.52,2155 6078.82,2174.71 5693.5,2174.71 5690.19,2178.02 5690.19,2400.04 5698.52,2408.37 5698.52,2661.36 5715.86,2678.69 5715.86,2782.71 5639.19,2859.37 5639.19,2908.37 5665.19,2934.37 5665.19,3183.37 5633.19,3215.37 5633.19,3235.71 ; 5598.49,3861.17 cw(c5568.98,3831.66) 5610.71,3831.66 5610.71,3812.16
  MidLayer2 w4: v1(5645,3305) 5656.19,3316.19 5656.19,3404.67 5673.52,3422 v1(5673.52,3454.04) ; v1@5666.81,3447.32 cw(c5650.59,3431.11) 5673.52,3431.11 cw(c5696.46,3431.11) v1@5680.24,3447.32 ; v1@5669.64,3450.15 cw(c5660.25,3440.76) 5673.52,3440.76 cw(c5686.8,3440.76) v1@5677.41,3450.15
  Bottom Layer w8: v5@7425.6,877.24 ccw(c7415.36,887.49) 7429.84,887.49 ccw(c7444.33,887.48) v5@7434.09,877.24 ; v5(7429.84,873) U19.36@7429.84,904.33
DBUSB.FLAGA: U8.AC17 U19.29 | length 4843.5
  Top Layer w4: U8.AC17@5527.8,3808.48 cw(c5527.8,3790.38) 5540.6,3803.18 cw(c5553.4,3815.98) U8.AC17@5535.3,3815.98 ; U8.AC17@5527.8,3808.64 cw(c5527.8,3790.92) 5540.33,3803.45 cw(c5552.86,3815.98) U8.AC17@5535.14,3815.98 ; U8.AC17@5527.8,3815.98 v3(5547.48,3796.3) ; v1@5590,3290.5 cw(c5590,3246.89) 5620.84,3277.73 ; v1@5590,3294.5 cw(c5590,3260.54) 5614.01,3284.55 ; v1@5590,3298.5 cw(c5590,3274.2) 5607.18,3291.38 ; v1(5590,3300) 5596.15,3300 5598.52,3302.37 5598.52,3300.04 5656.86,3241.71 ; v1@5652.02,3233.22 ccw(c5646.99,3241.71) 5656.86,3241.71 ; v1(5656.86,3225.04) 5656.86,3241.71 ; v1@5661.7,3233.22 cw(c5666.73,3241.71) 5656.86,3241.71 ; 5534.68,3809.1 cw(c5521.87,3796.3) 5539.98,3796.3 ccw(c5521.87,3796.3) 5534.68,3809.1 ; 5534.68,3809.1 ccw(c5547.48,3821.91) 5547.48,3803.8 cw(c5547.48,3821.91) 5534.68,3809.1
  MidLayer1 w4: v3@5542.29,3791.11 cw(c5529.75,3778.57) 5547.48,3778.57 cw(c5565.21,3778.57) v3@5552.67,3791.11 ; v3(5547.48,3796.3) 5547.48,3718.62 5547.48,3670 5547.48,3660 5547.48,3565.83 5550.86,3562.45 5550.86,3531.52 5567.5,3514.87 5567.5,3415.73 5590,3393.23 v1(5590,3300) ; v1@5583.28,3306.72 ccw(c5567.06,3322.93) 5590,3322.93 ccw(c5612.93,3322.93) v1@5596.72,3306.72 ; v1@5586.11,3303.89 ccw(c5576.72,3313.28) 5590,3313.28 ccw(c5603.28,3313.28) v1@5593.89,3303.89 ; v1@5656.86,3215.54 cw(c5656.86,3192.61) 5673.08,3208.82 cw(c5689.29,3225.04) v1@5666.36,3225.04 ; v1@5656.86,3219.54 cw(c5656.86,3206.26) 5666.25,3215.65 cw(c5675.64,3225.04) v1@5662.36,3225.04 ; v1(5656.86,3225.04) 5673.52,3208.37 5673.52,2893.33 5681.86,2885 5681.86,2866.71 5723.86,2824.71 5723.86,2675.37 5706.86,2658.37 5706.86,2341.71 5739.5,2309.06 5739.5,2209.06 5756.86,2191.71 6090.19,2191.71 6106.86,2175.04 6106.86,1869.08 6390.81,1585.13 6390.81,1304.5 6372.52,1286.21 6372.52,1146.3 6627.11,891.71 v1(7140.19,891.71) ; v1@7133.47,884.99 ccw(c7117.26,868.77) 7117.26,891.71 ccw(c7117.26,914.64) v1@7133.47,898.43 ; v1@7136.3,887.82 ccw(c7126.91,878.43) 7126.91,891.71 ccw(c7126.91,904.99) v1@7136.3,895.6 ; 5547.48,3778.19 cw(c5565.59,3778.19) 5552.78,3791 ccw(c5565.59,3778.19) 5547.48,3778.19 ; 5547.48,3778.19 ccw(c5529.37,3778.19) 5542.18,3791 cw(c5529.37,3778.19) 5547.48,3778.19
  Bottom Layer w4: v1(7140.19,891.71) 7156.86,908.37 7292.05,908.37 U19.29@7292.05,904.33 ccw(c7282.28,894.57) 7282.28,908.37 ; v1@7140.19,897.21 ccw(c7140.19,910.49) 7149.58,901.1 ccw(c7158.97,891.71) v1@7145.69,891.71 ; v1@7140.19,901.21 ccw(c7140.19,924.14) 7156.41,907.93 ccw(c7172.63,891.71) v1@7149.69,891.71 ; 7272.63,908.37 cw(c7272.63,884.91) U19.29@7289.22,901.5
DBUSB.FLAGB: U8.AB17 U19.30 | length 4974
  Top Layer w4: U8.AB17@5527.8,3847.85 cw(c5527.8,3829.75) 5540.6,3842.55 cw(c5553.4,3855.35) U8.AB17@5535.3,3855.35 ; U8.AB17@5527.8,3848.01 cw(c5527.8,3830.29) 5540.33,3842.82 cw(c5552.86,3855.35) U8.AB17@5535.14,3855.35 ; U8.AB17@5527.8,3855.35 v3(5547.48,3835.67) ; 5534.68,3848.47 cw(c5521.87,3835.67) 5539.98,3835.67 ccw(c5521.87,3835.67) 5534.68,3848.47 ; 5534.68,3848.47 ccw(c5547.48,3861.28) 5547.48,3843.17 cw(c5547.48,3861.28) 5534.68,3848.47
  MidLayer1 w4: v3@5546.83,3828.2 cw(c5545.25,3810.16) 5559.12,3821.8 cw(c5572.99,3833.44) v3@5554.95,3835.02 ; 5558.87,3822.09 cw(c5548.94,3812.16) 5562.99,3812.16 ; 5562.99,3798.23 5562.99,3812.16 ; v1@5580.69,2800.04 ccw(c5557.76,2800.04) 5573.97,2816.26 ccw(c5590.19,2832.48) v1@5590.19,2809.54 ; v1@5584.69,2800.04 ccw(c5571.41,2800.04) 5580.8,2809.43 ccw(c5590.19,2818.82) v1@5590.19,2805.54 ; v1(5590.19,2800.04) 5523.19,2867.04 5523.19,2957.04 5565.19,2999.04 5565.19,3173.67 5609.19,3217.67 5609.19,3316.57 5616.19,3323.57 5616.19,3378.36 5575.5,3419.05 5575.5,3518.19 5558.86,3534.83 5558.86,3641.29 5562.99,3645.43 5562.99,3660 5562.99,3670 5562.99,3718.62 5562.99,3812.16 ; v1@5675.14,2759.99 cw(c5658.92,2743.77) 5681.86,2743.77 cw(c5704.79,2743.77) v1@5688.57,2759.99 ; v1@5677.97,2762.82 cw(c5668.58,2753.43) 5681.86,2753.43 cw(c5695.14,2753.43) v1@5685.75,2762.82 ; v1(5681.86,2766.71) 5681.86,2716.71 5690.19,2708.37 5690.19,2411.35 5681.86,2403.02 5681.86,2175.04 5690.19,2166.71 6073.19,2166.71 6089.86,2150.04 6089.86,1863.45 6374.81,1578.5 6374.81,1389.81 6339.88,1354.88 6339.88,1290.12 6356.52,1273.48 6356.52,1139.67 6654.48,841.71 7248.52,841.71 7279.82,873 v5(7311.73,873) ; v5@7306.08,867.34 ccw(c7292.42,853.68) 7292.42,873 ccw(c7292.42,892.31) v5@7306.08,878.66
  Bottom Layer w4: v1(5590.19,2800.04) 5648.52,2800.04 v1(5681.86,2766.71) ; v1@5594.08,2796.15 cw(c5603.47,2786.76) 5603.47,2800.04 cw(c5603.47,2813.32) v1@5594.08,2803.93 ; v1@5596.91,2793.32 cw(c5613.13,2777.11) 5613.13,2800.04 cw(c5613.13,2822.98) v1@5596.91,2806.76 ; v1@5672.36,2766.71 ccw(c5649.42,2766.71) 5665.64,2782.93 ccw(c5681.86,2799.14) v1@5681.86,2776.21 ; v1@5676.36,2766.71 ccw(c5663.08,2766.71) 5672.47,2776.1 ccw(c5681.86,2785.49) v1@5681.86,2772.21
  Bottom Layer w8: v5@7307.49,877.24 ccw(c7297.25,887.49) 7311.73,887.49 ccw(c7326.22,887.48) v5@7315.97,877.24 ; v5(7311.73,873) U19.30@7311.73,904.33
DBUSB.FLAGC: U8.AA20 U19.31 | length 4486.6
  Top Layer w4: U8.AA20@5645.91,3887.22 cw(c5645.91,3869.12) 5658.71,3881.92 cw(c5671.51,3894.72) U8.AA20@5653.41,3894.72 ; U8.AA20@5645.91,3887.38 cw(c5645.91,3869.66) 5658.44,3882.19 cw(c5670.97,3894.72) U8.AA20@5653.25,3894.72 ; U8.AA20@5645.91,3894.72 v3(5665.59,3875.04) ; 5652.79,3887.84 cw(c5639.98,3875.04) 5658.09,3875.04 ccw(c5639.98,3875.04) 5652.79,3887.84 ; 5652.79,3887.84 ccw(c5665.59,3900.65) 5665.59,3882.54 cw(c5665.59,3900.65) 5652.79,3887.84
  MidLayer1 w4: v3@5664.29,3867.65 cw(c5661.14,3849.82) 5675.98,3860.21 ; v3@5672.98,3873.74 ccw(c5690.81,3870.59) 5675.98,3860.21 ; 5689.45,3798.23 5689.45,3812.16 ; v5@7331.42,927.66 cw(c7331.42,908.35) 7345.07,922 cw(c7358.73,935.66) v5@7339.42,935.66 ; v5(7331.42,935.66) 7350.37,916.71 7415.19,916.71 7431.86,933.37 7431.86,958.37 7415.23,975 7296.71,975 7105,1166.71 6998.52,1166.71 6793.52,1371.71 6793.52,1716.71 6782.86,1727.37 6529.52,1727.37 6215.19,2041.71 6215.19,2333.37 6148.52,2400.04 6076.51,2400.04 5981.52,2495.02 5981.52,2570.63 5906.86,2645.3 5906.86,2762.67 5913.69,2769.5 5913.69,2797.25 5906.86,2804.08 5906.86,2826.04 5915.19,2834.37 5915.19,2905.39 5942.19,2932.39 5942.19,3017.69 5922.19,3037.69 5922.19,3220.73 5956.86,3255.39 5956.86,3266.04 5970,3279.18 5970,3306.54 5923.52,3353.02 5923.52,3462.37 5868.86,3517.04 5776.84,3517.04 5740.19,3553.69 5740.19,3585.71 5705.64,3620.26 5689.45,3636.44 5689.45,3660 5689.45,3670 5689.45,3718.62 5689.45,3738.04 5689.45,3812.16 ; 5675.98,3860.21 5683.06,3851.63 cw(c5665.68,3835.41) 5689.45,3835.41 5689.45,3812.16
  Bottom Layer w8: v5@7327.17,931.42 cw(c7316.93,921.18) 7331.42,921.18 cw(c7345.9,921.18) v5@7335.66,931.42 ; U19.31@7331.42,904.33 v5(7331.42,935.66)
DBUSB.FLAGD_CS_N: U8.AE20 U19.40 | length 4553.5
  Top Layer w4: 5710.37,3470.14 cw(c5690.27,3450.04) v1@5718.69,3450.04 ; 5715.85,3464.65 ccw(c5728.19,3476.99) v1@5728.19,3459.54 ; 5717.19,3463.31 cw(c5703.92,3450.04) v1@5722.69,3450.04 ; v1@5719.86,3450.04 v1(5728.19,3450.04) 5728.19,3452.31 5699.19,3481.31 5699.19,3501 5699.19,3513.44 5655,3557.63 5655,3566.23 5655,3590 5655,3612.25 5661.41,3618.66 5661.41,3660 5661.41,3670 5661.41,3717.53 ; 5658.44,3724.71 cw(c5651.26,3717.53) 5661.41,3717.53 ; 5658.44,3724.71 cw(c5651.26,3717.53) 5661.41,3717.53 ; 5658.44,3724.71 ccw(c5645.91,3712.17) 5645.91,3729.9 cw(c5645.91,3712.17) 5658.44,3724.71 ; 5658.44,3724.71 cw(c5670.97,3737.24) 5653.25,3737.24 ccw(c5670.97,3737.24) 5658.44,3724.71
  MidLayer1 w4: v1(5728.19,3450.04) 5728.19,3441.71 5790.19,3379.71 5790.19,3265.06 5755.86,3230.73 5755.86,3070.65 5840.5,2986 5840.5,2815.81 5847.36,2808.95 5847.36,2768.83 5874.36,2741.83 5874.36,2684.46 5874.19,2684.29 5874.19,2633.01 5874.04,2632.86 5948.52,2558.37 5948.52,2280.37 5970.52,2258.37 6173.52,2258.37 6190.19,2241.71 6190.19,2029.41 6390.19,1829.41 6390.19,1631 6422.81,1598.38 6422.81,1254.82 6431.63,1246 6824.58,1246 7087.21,983.37 7156.86,983.37 v1(7181.86,958.37) ; v1@7172.36,958.37 ccw(c7149.42,958.37) 7165.64,974.59 ccw(c7181.86,990.81) v1@7181.86,967.87 ; v1@7176.36,958.37 ccw(c7163.08,958.37) 7172.47,967.76 ccw(c7181.86,977.15) v1@7181.86,963.87
  MidLayer2 w4: v1(7181.86,958.37) 7501.63,958.37 7508.58,951.42 v5(7508.58,873) ; v1@7185.75,954.49 cw(c7195.14,945.1) 7195.14,958.37 cw(c7195.14,971.65) v1@7185.75,962.26 ; v1@7188.57,951.66 cw(c7204.79,935.44) 7204.79,958.37 cw(c7204.79,981.31) v1@7188.57,965.09 ; v5@7502.93,878.66 ccw(c7489.27,892.31) 7508.58,892.31 ccw(c7527.9,892.31) v5@7514.24,878.66 ; v5@7506.86,873 v5(7508.58,873) ; v5@7510,874.42 v5(7508.58,873)
  Bottom Layer w8: v5@7504.34,877.24 ccw(c7494.1,887.49) 7508.58,887.49 ccw(c7523.07,887.48) v5@7512.83,877.24 ; v5(7508.58,873) U19.40@7508.58,904.33
DBUSB.IFCLK: R112.1 U8.V14 | length 5175.1
  Top Layer w4: U8.V14@5409.69,4005.33 cw(c5409.69,3987.23) 5422.49,4000.03 cw(c5435.29,4012.83) U8.V14@5417.19,4012.83 ; U8.V14@5409.69,4005.49 cw(c5409.69,3987.77) 5422.22,4000.3 cw(c5434.75,4012.83) U8.V14@5417.03,4012.83 ; U8.V14@5409.69,4012.83 v3(5429.37,3993.15) ; 5416.57,4005.95 cw(c5403.76,3993.15) 5421.87,3993.15 ccw(c5403.76,3993.15) 5416.57,4005.95 ; 5416.57,4005.95 ccw(c5429.37,4018.76) 5429.37,4000.65 cw(c5429.37,4018.76) 5416.57,4005.95
  MidLayer1 w4: v1@5382.47,3643.32 cw(c5366.26,3627.11) 5389.19,3627.11 cw(c5412.13,3627.11) v1@5395.91,3643.32 ; v1@5385.3,3646.15 cw(c5375.91,3636.76) 5389.19,3636.76 cw(c5402.47,3636.76) v1@5393.08,3646.15 ; v1(5389.19,3650.04) 5389.19,3618.34 5389.86,3617.67 5389.86,3570.02 5407.7,3552.18 5407.7,3472.26 5415.19,3464.78 5415.19,3408.37 5473.86,3349.71 5473.86,3233.04 5498.52,3208.37 5498.52,3195.37 5490.19,3187.04 5489.68,3187.04 ; 5489.68,3186.53 5462.99,3186.53 5448.52,3172.06 5448.52,2964.25 5434.78,2950.5 5434.44,2950.5 5419.5,2935.56 5419.5,2935.22 5397.52,2913.25 5397.52,2742.71 5440.19,2700.04 5440.19,2578.02 5456.86,2561.35 5456.86,2422.06 5423.52,2388.73 5423.52,1775.04 5831.86,1366.71 5831.86,1275.04 5848.52,1258.37 5939.52,1258.37 6522.86,675.04 6781.86,675.04 6790.19,683.37 v1(7098.52,683.37) ; v1@7091.81,676.66 ccw(c7075.59,660.44) 7075.59,683.37 ccw(c7075.59,706.31) v1@7091.81,690.09 ; v1@7094.64,679.49 ccw(c7085.25,670.1) 7085.25,683.37 ccw(c7085.25,696.65) v1@7094.64,687.26
  Bottom Layer w4: v1(5389.19,3650.04) 5442.04,3650.04 5444.88,3652.88 5444.88,3660 5444.88,3670 5444.88,3876.1 5444.88,3969.64 ccw(c5430.83,3969.64) 5440.76,3979.57 ; v1@5393.08,3646.15 cw(c5402.47,3636.76) 5402.47,3650.04 cw(c5402.47,3663.32) v1@5393.08,3653.93 ; v1@5395.91,3643.32 cw(c5412.13,3627.11) 5412.13,3650.04 cw(c5412.13,3672.98) v1@5395.91,3656.76 ; v3@5428.72,3985.68 cw(c5427.14,3967.64) 5441.01,3979.28 cw(c5454.88,3990.92) v3@5436.84,3992.5 ; v1@7091.81,676.66 cw(c7075.59,660.44) 7098.52,660.44 cw(c7121.46,660.44) v1@7105.24,676.66 ; v1@7094.64,679.49 cw(c7085.25,670.1) 7098.52,670.1 cw(c7111.8,670.1) v1@7102.41,679.49 ; v1(7098.52,683.37) 7098.52,611.48 7115,595 R112.1@7153.82,595 ; R112.1@7147.23,588.41 ccw(c7131.32,572.5) 7131.32,595 ccw(c7131.32,617.5) R112.1@7147.23,601.59 ; R112.1@7150.06,591.24 ccw(c7140.98,582.16) 7140.98,595 ccw(c7140.98,607.84) R112.1@7150.06,598.76
DBUSB.INT_N: R115.1 U8.AF22 U19.34 | length 4507.5
  Top Layer w4: U8.AF22@5719.34,3692.57 cw(c5706.54,3679.77) 5724.65,3679.77 cw(c5742.75,3679.77) U8.AF22@5729.95,3692.57 ; U8.AF22@5719.45,3692.68 cw(c5706.92,3680.15) 5724.65,3680.15 cw(c5742.37,3680.15) U8.AF22@5729.84,3692.68 ; U8.AF22@5724.65,3697.87 5724.65,3670 5724.65,3660 5724.65,3565.19 5731.52,3558.31 5731.52,3533.71 5740.19,3525.04 5748.52,3516.71 v1(5748.52,3491.71) ; v1@5741.81,3498.43 ccw(c5725.59,3514.64) 5748.52,3514.64 ccw(c5771.46,3514.64) v1@5755.24,3498.43 ; v1@5744.64,3495.6 ccw(c5735.25,3504.99) 5748.52,3504.99 ccw(c5761.8,3504.99) v1@5752.41,3495.6 ; v1(7181.86,1033.37) 7375,1033.37 7390.47,1017.9 v5(7390.47,873) ; v1@7185.75,1029.49 cw(c7195.14,1020.1) 7195.14,1033.37 cw(c7195.14,1046.65) v1@7185.75,1037.26 ; v1@7188.57,1026.66 cw(c7204.79,1010.44) 7204.79,1033.37 cw(c7204.79,1056.31) v1@7188.57,1040.09 ; v5@7384.82,878.66 ccw(c7371.16,892.32) 7390.47,892.32 ccw(c7409.78,892.31) v5@7396.13,878.66
  MidLayer1 w4: v1@5748.52,3482.21 cw(c5748.52,3459.27) 5764.74,3475.49 cw(c5780.96,3491.71) v1@5758.02,3491.71 ; v1@5748.52,3486.21 cw(c5748.52,3472.93) 5757.91,3482.32 cw(c5767.3,3491.71) v1@5754.02,3491.71 ; v1(5748.52,3491.71) 5765,3475.23 5765,3428.21 5806.86,3386.36 5806.86,3289.71 5848.94,3247.63 5848.94,3222.74 5815.19,3188.99 5815.19,3022.63 5848.52,2989.29 5848.52,2819.1 5855.36,2812.27 5855.36,2772.14 5882.36,2745.15 5882.36,2681.15 5882.19,2680.98 5882.19,2636.02 5956.86,2561.35 5956.86,2291.71 5981.86,2266.71 6181.86,2266.71 6198.52,2250.04 6198.52,2032.39 6398.52,1832.39 6398.52,1659.71 6495.42,1562.81 6507.38,1562.81 6517.81,1552.38 6517.81,1540.42 6566.86,1491.37 6666.52,1491.37 6675.19,1500.04 6675.19,1523.04 6681.86,1529.71 6751.86,1529.71 6753.52,1528.04 6753.52,1461.71 6781.86,1433.37 6781.86,1300.04 6931.86,1150.04 7065.19,1150.04 v1(7181.86,1033.37) ; v1@7172.36,1033.37 ccw(c7149.42,1033.37) 7165.64,1049.59 ccw(c7181.86,1065.81) v1@7181.86,1042.87 ; v1@7176.36,1033.37 ccw(c7163.08,1033.37) 7172.47,1042.76 ccw(c7181.86,1052.15) v1@7181.86,1038.87
  Bottom Layer w4: v1(7181.86,1033.37) 7196.18,1019.05 R115.1@7196.18,990 ; R115.1@7189.59,997.08 ccw(c7173.68,1012.99) 7196.18,1012.99 ccw(c7218.68,1012.99) R115.1@7202.77,997.08 ; R115.1@7192.42,994.25 ccw(c7183.34,1003.33) 7196.18,1003.33 ccw(c7209.02,1003.33) R115.1@7199.94,994.25
  Bottom Layer w8: v5@7386.23,877.24 ccw(c7375.99,887.49) 7390.47,887.49 ccw(c7404.96,887.48) v5@7394.72,877.24 ; v5(7390.47,873) U19.34@7390.47,904.33
DBUSB.PKTEND: U8.AE21 U19.39 | length 5308.4
  Top Layer w4: v1(5698.86,3550.37) 5701.14,3552.66 5701.14,3613.86 5700.78,3614.22 5700.78,3660 5700.78,3670 5700.78,3717.53 ; 5697.81,3724.71 cw(c5690.63,3717.53) 5700.78,3717.53 ; 5697.81,3724.71 cw(c5690.63,3717.53) 5700.78,3717.53 ; 5697.81,3724.71 ccw(c5685.28,3712.17) 5685.28,3729.9 cw(c5685.28,3712.17) 5697.81,3724.71 ; 5697.81,3724.71 cw(c5710.34,3737.24) 5692.62,3737.24 ccw(c5710.34,3737.24) 5697.81,3724.71
  MidLayer1 w4: v5@7483.24,941.32 ccw(c7469.58,954.98) 7488.9,954.98 ccw(c7508.21,954.98) v5@7494.55,941.32 ; v1(7815.19,3108.37) 7831.86,3108.37 ; v1@7823.36,3103.53 cw(c7831.86,3098.51) 7831.86,3108.37 ; v1@7823.36,3113.22 ccw(c7831.86,3118.24) 7831.86,3108.37 ; v5@7488.9,943.33 v5(7488.9,935.66) 7488.9,933.37 7489.19,933.37 7490.19,934.37 7490.19,942.04 v5@7488.9,943.33 ; v5@7488.9,943.33 7488.9,984.63 7473.52,1000 7473.52,1466.71 7781.86,1775.04 7781.86,1869.65 7778.69,1872.81 7778.69,1944.87 7848.52,2014.71 7848.52,2258.37 7856.86,2266.71 7856.86,2333.37 7831.86,2358.37 7831.86,2966.71 7848.52,2983.37 7848.52,3091.71 7831.86,3108.37
  MidLayer2 w4: v1(5698.86,3550.37) 5698.86,3486.69 5707.19,3478.36 5707.19,3416.37 5723.52,3400.04 5861.86,3400.04 5911.86,3450.04 v1(5965.19,3450.04) ; v1@5958.47,3443.32 ccw(c5942.26,3427.11) 5942.26,3450.04 ccw(c5942.26,3472.98) v1@5958.47,3456.76 ; v1@5961.3,3446.15 ccw(c5951.91,3436.76) 5951.91,3450.04 ccw(c5951.91,3463.32) v1@5961.3,3453.93
  Bottom Layer w4: v1(5965.19,3450.04) 6189.52,3450.04 6190.19,3450.71 6247.86,3450.71 6256.86,3441.71 6583.19,3441.71 6616.52,3475.04 6672.19,3475.04 6705.52,3441.71 6834.23,3441.71 6859.56,3416.37 7173.86,3416.37 7198.52,3391.71 7298.52,3391.71 7509.64,3180.59 7520.23,3170 7610,3170 7625,3185 7738.37,3185 7815,3108.37 v1(7815.19,3108.37) ; 7798.65,3124.73 ccw(c7815.19,3141.27) v1@7815.19,3117.87 ; 7799.11,3124.27 cw(c7783.21,3108.37) v1@7805.69,3108.37 ; 7805.48,3117.9 ccw(c7815.19,3127.61) v1@7815.19,3113.87 ; 7805.94,3117.44 cw(c7796.87,3108.37) v1@7809.69,3108.37
  Bottom Layer w8: v5@7484.66,931.42 cw(c7474.41,921.18) 7488.9,921.18 cw(c7503.38,921.18) v5@7493.14,931.42 ; U19.39@7488.9,904.33 v5(7488.9,935.66)
DBUSB.RD_N: U8.U16 U19.1 | length 6740.7
  Top Layer w4: U8.U16@5488.43,4044.7 cw(c5488.43,4026.6) 5501.23,4039.4 cw(c5514.03,4052.2) U8.U16@5495.93,4052.2 ; U8.U16@5488.43,4044.86 cw(c5488.43,4027.14) 5500.96,4039.67 cw(c5513.49,4052.2) U8.U16@5495.77,4052.2 ; U8.U16@5488.43,4052.2 v3(5508.11,4032.52) ; 5495.31,4045.32 cw(c5482.5,4032.52) 5500.61,4032.52 ccw(c5482.5,4032.52) 5495.31,4045.32 ; 5495.31,4045.32 ccw(c5508.11,4058.13) 5508.11,4040.02 cw(c5508.11,4058.13) 5495.31,4045.32
  MidLayer1 w4: v1@6941.61,2776.86 ccw(c6926.51,2762.61) 6926.51,2783.37 ; v1@6941.61,2789.89 cw(c6926.51,2804.14) 6926.51,2783.37 ; v1@6944.52,2779.6 ccw(c6935.78,2771.35) 6935.78,2783.37 ccw(c6935.78,2795.4) v1@6944.52,2787.15 ; v1(6948.52,2783.37) 6926.51,2783.37 ; v1@7575.14,984.99 ccw(c7558.92,968.77) 7558.92,991.71 ccw(c7558.92,1014.64) v1@7575.14,998.43 ; v1@7577.97,987.82 ccw(c7568.58,978.43) 7568.58,991.71 ccw(c7568.58,1004.99) v1@7577.97,995.6 ; v1(7581.86,991.71) 7556.86,991.71 7531.86,1016.71 7531.86,1083.37 7515.19,1100.04 7498.52,1100.04 7481.86,1083.37 7481.86,1010 7506.86,985 7506.86,925.04 7498.52,916.71 7474.19,916.71 7465.86,925.04 7465.86,950.04 7456.86,959.04 7456.86,1225.04 7431.86,1250.04 7006.86,1250.04 6990.19,1266.71 6990.19,1490.04 6989.19,1491.04 6920.19,1491.04 6911.19,1500.04 6911.19,1850.04 6894.52,1866.71 6731.86,1866.71 6715.19,1883.37 6715.19,1916.71 6707.19,1924.71 6683.52,1924.71 6674.86,1933.37 6674.86,2308.37 6691.52,2325.04 6712.19,2325.04 6765.19,2378.04 6765.19,2610.75 6906.86,2752.41 6906.86,2763.73 6926.51,2783.37
  MidLayer2 w4: v1(6081.86,3491.71) 6198.52,3491.71 6220.09,3470.14 6281.86,3408.37 6315.19,3408.37 6373.52,3350.04 6668.5,3350.04 6715.19,3303.35 6715.19,3233.37 6948.52,3000.04 v1(6948.52,2783.37) ; v1@6085.75,3487.82 cw(c6095.14,3478.43) 6095.14,3491.71 cw(c6095.14,3504.99) v1@6085.75,3495.6 ; v1@6088.57,3484.99 cw(c6104.79,3468.77) 6104.79,3491.71 cw(c6104.79,3514.64) v1@6088.57,3498.43 ; v1@6941.81,2790.09 ccw(c6925.59,2806.31) 6948.52,2806.31 ccw(c6971.46,2806.31) v1@6955.24,2790.09 ; v1@6944.64,2787.26 ccw(c6935.25,2796.65) 6948.52,2796.65 ccw(c6961.8,2796.65) v1@6952.41,2787.26 ; v1@7575.14,984.99 cw(c7558.92,968.77) 7581.86,968.77 cw(c7604.79,968.77) v1@7588.57,984.99 ; v1@7577.97,987.82 cw(c7568.58,978.43) 7581.86,978.43 cw(c7595.14,978.43) v1@7585.75,987.82 ; v1(7581.86,991.71) 7581.86,618.14 7599.96,600.04 v1(7631.86,600.04) ; v1@7625.14,593.32 ccw(c7608.92,577.11) 7608.92,600.04 ccw(c7608.92,622.98) v1@7625.14,606.76 ; v1@7627.97,596.15 ccw(c7618.58,586.76) 7618.58,600.04 ccw(c7618.58,613.32) v1@7627.97,603.93
  Bottom Layer w4: v3@5507.46,4025.05 cw(c5505.88,4007.01) 5519.75,4018.65 ; v3@5515.58,4031.87 ccw(c5533.62,4030.29) 5519.75,4018.65 ; 5574.95,3534.95 5649.9,3460 5649.9,3436.42 5661.23,3425.08 5765.76,3425.08 5772.46,3418.37 5791.86,3418.37 5873.52,3500.04 5955,3500.04 5979.84,3500 5988.13,3491.71 v1(6081.86,3491.71) ; 5575,3535 5554.99,3555.01 5554.99,3626.98 5531.97,3650 5531.97,3660 5531.97,3670 5531.97,3876.1 5531.97,3895.52 5531.97,3969.64 5531.97,3989.14 ccw(c5490.24,3989.14) 5519.75,4018.65 ; v1@6075.14,3484.99 ccw(c6058.92,3468.77) 6058.92,3491.71 ccw(c6058.92,3514.64) v1@6075.14,3498.43 ; v1@6077.97,3487.82 ccw(c6068.58,3478.43) 6068.58,3491.71 ccw(c6068.58,3504.99) v1@6077.97,3495.6 ; U19.1@7550.78,592.84 cw(c7568.16,575.46) 7568.16,600.04 ; 7558.51,600.04 ccw(c7558.51,585.12) U19.1@7547.95,595.67 7547.95,600.04 v1(7631.86,600.04) ; v1@7625.14,593.32 ccw(c7608.92,577.11) 7608.92,600.04 ccw(c7608.92,622.98) v1@7625.14,606.76 ; v1@7627.97,596.15 ccw(c7618.58,586.76) 7618.58,600.04 ccw(c7618.58,613.32) v1@7627.97,603.93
